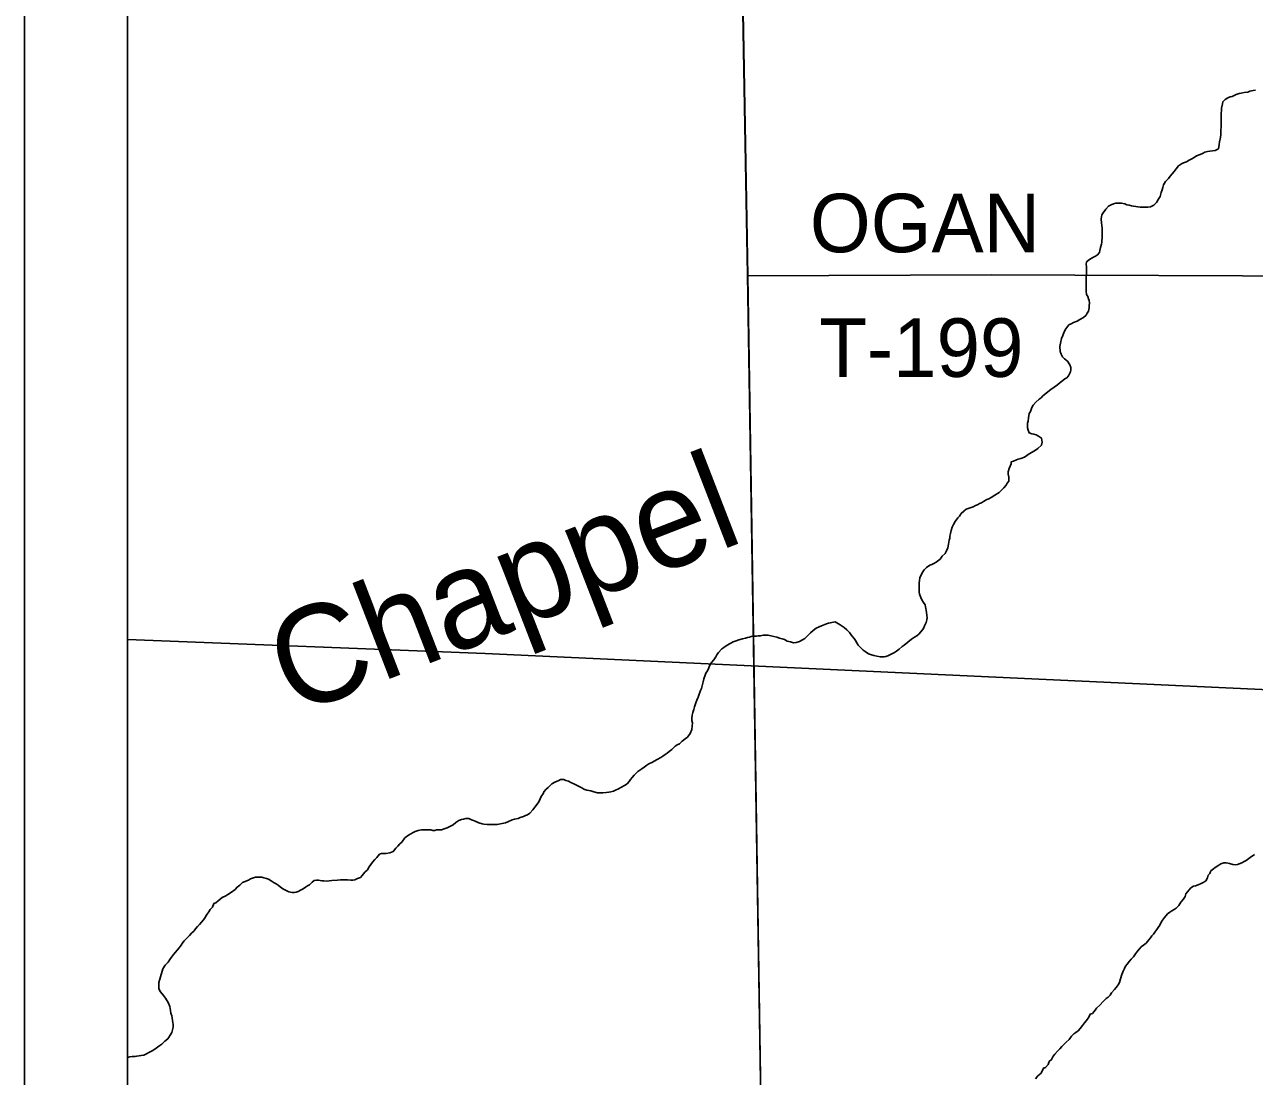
# Model space of a CAD drawing. Extents: x 0 to 34, y 0 to 22.
# Drawn here: x 2 to 3.195, y 17.941 to 18.962 of the extents above; entities that cross this region are included whole.
import ezdxf

# ---------------------------------------------------------------- set-up
doc = ezdxf.new("R2010")
doc.units = 0
for name, color, linetype in [('GM_X_Corporation', 7, 'Continuous'), ('GM_X_Minor_River', 7, 'Continuous'), ('GM_X_Minor_River_Text', 7, 'Continuous'), ('GM_X_Rail_Line', 7, 'Continuous'), ('GM_X_Township_Road', 7, 'Continuous'), ('GM_X_Township_Road_Text', 7, 'Continuous'), ('SH_Data', 7, 'Continuous')]:
    doc.layers.add(name, color=color, linetype=linetype)

msp = doc.modelspace()

# ---------------------------------------------------------------- linework, layer by layer
at = {"layer": 'GM_X_Corporation'}
for points in [[(3.1996, 20.2345), (3.1561, 20.2337), (3.1064, 20.2336), (3.0286, 20.2331), (3.0007, 20.2328), (2.9354, 20.2326), (2.8825, 20.2322), (2.8234, 20.2319), (2.7333, 20.2317), (2.6825, 20.2316), (2.6344, 20.2324), (2.5847, 20.2334), (2.535, 20.2346), (2.5164, 20.2351), (2.4604, 20.2364), (2.3921, 20.2383), (2.333, 20.2398), (2.2833, 20.2411), (2.246, 20.2419), (2.187, 20.2434), (2.1124, 20.2453), (2.1, 20.2456), (2.1, 14.1)], [(3.1996, 20.2345), (3.1561, 20.2337), (3.1064, 20.2336), (3.0286, 20.2331), (3.0007, 20.2328), (2.9354, 20.2326), (2.8825, 20.2322), (2.8234, 20.2319), (2.7333, 20.2317), (2.6825, 20.2316), (2.6883, 19.5017), (2.7024, 18.7188), (2.7184, 17.7156), (2.7304, 16.9599), (2.7477, 15.8824), (2.7366, 15.2014)]]:
    msp.add_lwpolyline(points, dxfattribs=at)
msp.add_lwpolyline([(2.1, 20.2456), (2.1, 15.2121), (2.7366, 15.2014), (2.7477, 15.8824), (2.7304, 16.9599), (2.7184, 17.7156), (2.7024, 18.7188), (2.6883, 19.5017), (2.6825, 20.2316), (2.6344, 20.2324), (2.5847, 20.2334), (2.535, 20.2346), (2.5164, 20.2351), (2.4604, 20.2364), (2.3921, 20.2383), (2.333, 20.2398), (2.2833, 20.2411), (2.246, 20.2419), (2.187, 20.2434), (2.1124, 20.2453)], close=True, dxfattribs=at)
at = {"layer": 'GM_X_Minor_River'}
for points in [[(3.196, 18.8986), (3.1937, 18.8982), (3.1903, 18.8974), (3.1884, 18.8967), (3.185, 18.8963), (3.182, 18.8956), (3.1801, 18.8952), (3.177, 18.8944), (3.1732, 18.8925), (3.1713, 18.8921), (3.169, 18.891), (3.1664, 18.8895), (3.1641, 18.8872), (3.1637, 18.8853), (3.1629, 18.8811), (3.1626, 18.8739), (3.1625, 18.8682), (3.1625, 18.8629), (3.1622, 18.8598), (3.1621, 18.8556), (3.1618, 18.8526), (3.161, 18.8484), (3.1606, 18.8457), (3.1599, 18.8416), (3.1568, 18.84), (3.1542, 18.8397), (3.1515, 18.8393), (3.1492, 18.8389), (3.1466, 18.8382), (3.1443, 18.837), (3.142, 18.8359), (3.1386, 18.8347), (3.1363, 18.8332), (3.134, 18.8317), (3.1313, 18.8306), (3.1287, 18.829), (3.126, 18.8279), (3.1241, 18.8271), (3.1211, 18.8249), (3.1188, 18.8222), (3.1169, 18.8195), (3.115, 18.8173), (3.1131, 18.815), (3.1112, 18.8127), (3.1085, 18.8097), (3.1066, 18.8066), (3.1059, 18.804), (3.1051, 18.8017), (3.1043, 18.799), (3.1032, 18.7952), (3.102, 18.7933), (3.0998, 18.7895), (3.0971, 18.7869), (3.0937, 18.7853), (3.0914, 18.785), (3.0891, 18.785), (3.0868, 18.785), (3.0838, 18.785), (3.0815, 18.7853), (3.0754, 18.7861), (3.0732, 18.7869), (3.0709, 18.7873), (3.069, 18.788), (3.0656, 18.7888), (3.0621, 18.7888), (3.0602, 18.7888), (3.058, 18.788), (3.0557, 18.7873), (3.053, 18.7857), (3.0504, 18.7831), (3.0477, 18.7793), (3.0465, 18.7774), (3.0458, 18.7736), (3.0462, 18.7694), (3.0465, 18.7675), (3.0469, 18.7641), (3.0469, 18.7618), (3.0469, 18.7595), (3.0469, 18.7568), (3.0469, 18.7546), (3.0465, 18.7527), (3.0465, 18.7508), (3.0461, 18.7489), (3.0454, 18.7458), (3.0446, 18.7428), (3.0442, 18.7409), (3.0419, 18.7382), (3.0397, 18.7371), (3.0378, 18.7359), (3.0347, 18.734), (3.0317, 18.7318), (3.0313, 18.7291), (3.0317, 18.7272), (3.0317, 18.7253)], [(3.0317, 18.7253), (3.0317, 18.7222), (3.0317, 18.7203), (3.0313, 18.7184), (3.0313, 18.7162), (3.0313, 18.7139), (3.0313, 18.712), (3.0313, 18.7101), (3.0313, 18.7074), (3.0313, 18.7051), (3.0313, 18.7032), (3.0316, 18.7002), (3.0328, 18.6983), (3.0335, 18.696), (3.0343, 18.6941), (3.0347, 18.6918), (3.0343, 18.6895), (3.0343, 18.6873), (3.0335, 18.6838), (3.0324, 18.6819), (3.0312, 18.68), (3.0286, 18.6778), (3.0252, 18.6759), (3.0225, 18.6743), (3.0191, 18.6728), (3.0168, 18.6717), (3.0145, 18.6705), (3.0115, 18.6667), (3.0099, 18.6637), (3.0088, 18.6603), (3.0073, 18.6572), (3.0065, 18.6527), (3.0058, 18.6496), (3.0061, 18.6447), (3.0069, 18.642), (3.0084, 18.6397), (3.0103, 18.6375), (3.0133, 18.6352), (3.0156, 18.6317), (3.0164, 18.6291), (3.0164, 18.6268), (3.016, 18.6249), (3.0152, 18.623), (3.0141, 18.6211), (3.0126, 18.6192), (3.0107, 18.6181), (3.0088, 18.6165), (3.0061, 18.6146), (3.0034, 18.6124), (3.0004, 18.6101), (2.997, 18.6078), (2.9894, 18.6017), (2.9875, 18.5998), (2.9856, 18.5983), (2.9825, 18.5956), (2.9799, 18.5926), (2.9787, 18.5903), (2.9772, 18.5865), (2.976, 18.5846), (2.9753, 18.5804), (2.9749, 18.577), (2.9745, 18.5751), (2.9745, 18.5725), (2.9745, 18.5705), (2.9749, 18.5683), (2.976, 18.5656), (2.9787, 18.5648), (2.9806, 18.5645), (2.9829, 18.5637), (2.9851, 18.5626), (2.9878, 18.5606), (2.9886, 18.5568), (2.9878, 18.5538), (2.9844, 18.5504), (2.9821, 18.5489), (2.979, 18.547), (2.976, 18.5454), (2.9737, 18.5439), (2.9714, 18.542), (2.968, 18.5409), (2.9654, 18.5401), (2.9635, 18.5394), (2.9608, 18.5382), (2.9585, 18.5375), (2.9585, 18.5356), (2.9566, 18.531), (2.9555, 18.528), (2.9555, 18.5257), (2.9562, 18.5226), (2.9562, 18.5188), (2.9547, 18.5169), (2.9536, 18.515), (2.9513, 18.5124), (2.949, 18.5101), (2.9467, 18.5078), (2.9425, 18.5052), (2.9391, 18.5029), (2.9368, 18.5017), (2.9349, 18.501), (2.9315, 18.4991), (2.9296, 18.4979)], [(2.9296, 18.4979), (2.9277, 18.4972), (2.9258, 18.496), (2.9239, 18.4953), (2.9216, 18.4938), (2.9186, 18.493), (2.9167, 18.4923), (2.9148, 18.4915), (2.9125, 18.4896), (2.9098, 18.4873), (2.9083, 18.485), (2.9068, 18.4831), (2.9041, 18.4797), (2.9026, 18.4767), (2.9011, 18.474), (2.9003, 18.471), (2.8995, 18.4679), (2.8988, 18.4653), (2.8988, 18.4634), (2.8984, 18.4615), (2.8976, 18.4577), (2.8969, 18.4542), (2.8957, 18.4512), (2.8942, 18.4485), (2.8915, 18.4459), (2.8896, 18.4432), (2.8855, 18.4402), (2.8832, 18.439), (2.8813, 18.4379), (2.8794, 18.4371), (2.8763, 18.4349), (2.874, 18.4326), (2.8725, 18.4307), (2.8714, 18.4284), (2.8699, 18.425), (2.8695, 18.4223), (2.8691, 18.42), (2.8691, 18.4166), (2.8691, 18.4132), (2.8691, 18.4113), (2.8695, 18.409), (2.8706, 18.406), (2.8717, 18.4037), (2.8733, 18.401), (2.8748, 18.3987), (2.8751, 18.3968), (2.8763, 18.3915), (2.8767, 18.3885), (2.877, 18.3866), (2.8767, 18.3843), (2.8759, 18.3816), (2.8744, 18.3782), (2.8732, 18.3759), (2.8721, 18.374), (2.869, 18.3706), (2.8668, 18.3687), (2.8645, 18.3672), (2.8618, 18.3653), (2.8546, 18.3596), (2.8527, 18.3584), (2.8496, 18.3558), (2.847, 18.3539), (2.8451, 18.3524), (2.8432, 18.3516), (2.8405, 18.3501), (2.8386, 18.3493), (2.8367, 18.3486), (2.8348, 18.3482), (2.8314, 18.3482), (2.828, 18.3489), (2.8249, 18.3497), (2.8219, 18.3505), (2.82, 18.3512), (2.8166, 18.3535), (2.8147, 18.3547), (2.812, 18.3573), (2.8097, 18.3596), (2.8086, 18.3619), (2.8071, 18.3642), (2.806, 18.3661), (2.8037, 18.3687), (2.8014, 18.3718), (2.7987, 18.3745), (2.7961, 18.3767), (2.7942, 18.3779), (2.7923, 18.3794), (2.7874, 18.3821), (2.7843, 18.3817), (2.7809, 18.3809), (2.779, 18.3802), (2.7759, 18.379), (2.7741, 18.3783), (2.7718, 18.3775), (2.7691, 18.376), (2.7661, 18.3737), (2.7634, 18.3714), (2.7607, 18.3688), (2.7581, 18.3661), (2.7558, 18.3646), (2.7528, 18.3631), (2.7497, 18.3623)], [(2.7497, 18.3623), (2.7471, 18.3619), (2.744, 18.3627), (2.741, 18.3635), (2.7383, 18.365), (2.736, 18.3658), (2.7334, 18.3665), (2.7307, 18.3673), (2.725, 18.3688), (2.7224, 18.3692), (2.7193, 18.3692), (2.7174, 18.3692), (2.7151, 18.3688), (2.7129, 18.3688), (2.711, 18.3684), (2.7087, 18.3684), (2.706, 18.3681), (2.7041, 18.3673), (2.7022, 18.3669), (2.7003, 18.3665), (2.6973, 18.3658), (2.6939, 18.3646), (2.6912, 18.3639), (2.6885, 18.3628), (2.6855, 18.3612), (2.6825, 18.3597), (2.6794, 18.3574), (2.6775, 18.3559), (2.6741, 18.3525), (2.6726, 18.3502), (2.6714, 18.3483), (2.6695, 18.3453), (2.6672, 18.3426), (2.6653, 18.3396), (2.6646, 18.3377), (2.6634, 18.3346), (2.6619, 18.3323), (2.6611, 18.3304), (2.66, 18.327), (2.6592, 18.324), (2.6577, 18.3175), (2.6566, 18.3156), (2.655, 18.3111), (2.6543, 18.3092), (2.6531, 18.3061), (2.652, 18.3035), (2.6516, 18.3015), (2.6509, 18.2996), (2.6501, 18.297), (2.6493, 18.2943), (2.6486, 18.2917), (2.6482, 18.2886), (2.6482, 18.2863), (2.6489, 18.2841), (2.6482, 18.2776), (2.6466, 18.2738), (2.644, 18.2704), (2.6417, 18.2685), (2.6387, 18.2662), (2.6364, 18.2639), (2.6341, 18.2628), (2.6322, 18.2616), (2.6288, 18.2582), (2.6261, 18.2563), (2.6242, 18.2548), (2.6223, 18.2533), (2.62, 18.2518), (2.6181, 18.2506), (2.6147, 18.2487), (2.6094, 18.2457), (2.6063, 18.2442), (2.6044, 18.243), (2.6018, 18.2411), (2.5995, 18.2396), (2.5957, 18.2369), (2.5923, 18.2335), (2.5904, 18.2312), (2.5888, 18.229), (2.5873, 18.2271), (2.5854, 18.2248), (2.5828, 18.2233), (2.5793, 18.2214), (2.5771, 18.2202), (2.574, 18.2187), (2.5721, 18.2179), (2.5694, 18.2172), (2.5675, 18.2168), (2.5649, 18.2164), (2.5618, 18.2161), (2.5592, 18.2161), (2.5565, 18.2161), (2.5531, 18.2172), (2.5501, 18.218), (2.5482, 18.2183), (2.5463, 18.2187), (2.5432, 18.2199), (2.5413, 18.221), (2.5368, 18.2233), (2.5337, 18.2248), (2.5307, 18.2263), (2.5284, 18.2275)], [(2.5284, 18.2275), (2.5258, 18.2283), (2.5239, 18.229), (2.5208, 18.229), (2.5189, 18.2283), (2.5151, 18.2267), (2.5121, 18.2248), (2.5087, 18.2214), (2.5068, 18.2199), (2.5045, 18.2172), (2.5037, 18.2153), (2.5022, 18.2134), (2.501, 18.2104), (2.4995, 18.2074), (2.498, 18.2051), (2.4957, 18.2024), (2.4938, 18.1998), (2.4908, 18.1963), (2.4885, 18.1948), (2.4866, 18.1941), (2.4847, 18.1933), (2.4813, 18.1922), (2.4794, 18.1914), (2.4759, 18.1906), (2.4737, 18.1899), (2.4695, 18.188), (2.4672, 18.1872), (2.4607, 18.1857), (2.4588, 18.1853), (2.4569, 18.1853), (2.4531, 18.1853), (2.4512, 18.1853), (2.4493, 18.1853), (2.4463, 18.1857), (2.4444, 18.1861), (2.4414, 18.1872), (2.4379, 18.1888), (2.436, 18.1892), (2.4341, 18.1899), (2.4315, 18.1911), (2.4288, 18.1911), (2.4265, 18.1907), (2.4246, 18.1903), (2.422, 18.1892), (2.4189, 18.1873), (2.4163, 18.185), (2.4144, 18.1842), (2.4106, 18.1823), (2.4075, 18.1812), (2.4049, 18.1804), (2.4022, 18.1801), (2.4003, 18.1801), (2.3984, 18.1797), (2.3965, 18.1797), (2.3946, 18.1801), (2.3923, 18.1801), (2.3904, 18.1801), (2.3885, 18.1804), (2.3855, 18.1801), (2.3825, 18.1797), (2.3794, 18.1785), (2.3775, 18.1778), (2.373, 18.1751), (2.3695, 18.1725), (2.3665, 18.1683), (2.3646, 18.1668), (2.3627, 18.1645), (2.3608, 18.1626), (2.3581, 18.1592), (2.3547, 18.158), (2.3513, 18.1573), (2.3494, 18.1573), (2.3467, 18.1573), (2.3448, 18.1565), (2.3422, 18.1535), (2.3402, 18.1516), (2.338, 18.1489), (2.3364, 18.1466), (2.3349, 18.1444), (2.333, 18.1413), (2.3307, 18.139), (2.3281, 18.136), (2.3262, 18.1341), (2.3235, 18.133), (2.3208, 18.1318), (2.3189, 18.1314), (2.317, 18.1314), (2.3136, 18.1318), (2.3117, 18.1318), (2.3087, 18.1318), (2.3068, 18.1318), (2.3041, 18.1315), (2.2984, 18.1311), (2.2958, 18.1307), (2.2939, 18.1303), (2.2908, 18.1307), (2.2889, 18.1307), (2.2855, 18.1315), (2.2836, 18.1315), (2.2813, 18.1311), (2.2794, 18.1296)], [(3.1948, 18.1562), (3.1907, 18.1535), (3.1869, 18.1505), (3.185, 18.1494), (3.1827, 18.1482), (3.1785, 18.1467), (3.1762, 18.1463), (3.1739, 18.1467), (3.1705, 18.1475), (3.1675, 18.1482), (3.1652, 18.1482), (3.1622, 18.1471), (3.1603, 18.146), (3.1568, 18.1437), (3.1549, 18.1425), (3.1526, 18.1403), (3.1515, 18.138), (3.15, 18.1361), (3.1492, 18.1338), (3.1477, 18.1307), (3.1458, 18.1296), (3.1431, 18.1281), (3.1401, 18.127), (3.1374, 18.1258), (3.1355, 18.1254), (3.1329, 18.1239), (3.1283, 18.1182), (3.1275, 18.1156), (3.1256, 18.1125), (3.1234, 18.1099), (3.1214, 18.1068), (3.1188, 18.1041), (3.1169, 18.103), (3.1146, 18.1015), (3.1127, 18.1004), (3.1104, 18.0988), (3.1074, 18.095), (3.1055, 18.0924), (3.104, 18.0901), (3.1028, 18.0878), (3.1013, 18.0855), (3.1001, 18.0836), (3.0982, 18.081), (3.0967, 18.0791), (3.0952, 18.0772), (3.0937, 18.0753), (3.0922, 18.0734), (3.0895, 18.0703), (3.0872, 18.0684), (3.0849, 18.0665), (3.083, 18.0646), (3.0811, 18.0623), (3.0792, 18.0597), (3.0773, 18.057), (3.075, 18.0547), (3.0735, 18.0528), (3.0712, 18.0498), (3.0697, 18.0479), (3.0686, 18.0456), (3.0674, 18.043), (3.0659, 18.0399), (3.0648, 18.0357), (3.0636, 18.0319), (3.0625, 18.0297), (3.0606, 18.027), (3.059, 18.0251), (3.056, 18.0221), (3.0545, 18.0198), (3.0526, 18.0179), (3.0507, 18.0164), (3.0476, 18.0133), (3.045, 18.0103), (3.0415, 18.0072), (3.04, 18.005)], [(2.2794, 18.1296), (2.2768, 18.1269), (2.2749, 18.1258), (2.273, 18.1246), (2.2707, 18.1231), (2.2688, 18.122), (2.2657, 18.1205), (2.2638, 18.1197), (2.2619, 18.1193), (2.26, 18.1193), (2.2566, 18.1201), (2.254, 18.1212), (2.2509, 18.1231), (2.2483, 18.125), (2.2464, 18.1266), (2.2445, 18.1277), (2.2426, 18.1288), (2.2395, 18.1307), (2.2369, 18.1323), (2.235, 18.133), (2.2323, 18.1338), (2.2304, 18.1342), (2.2281, 18.1342), (2.2262, 18.1342), (2.2243, 18.1342), (2.2213, 18.1334), (2.2194, 18.1327), (2.2175, 18.1315), (2.2118, 18.1292), (2.2091, 18.1266), (2.2065, 18.1247), (2.2046, 18.1224), (2.2011, 18.1197), (2.1973, 18.1175), (2.1954, 18.1163), (2.192, 18.1144), (2.1882, 18.1114), (2.1859, 18.1095), (2.184, 18.1087), (2.1825, 18.1053), (2.1802, 18.103), (2.1791, 18.1007), (2.1772, 18.0981), (2.1749, 18.0943), (2.1722, 18.0909), (2.17, 18.0882), (2.1681, 18.0863), (2.1661, 18.084), (2.1646, 18.0821), (2.1623, 18.0798), (2.1601, 18.0776), (2.157, 18.0745), (2.1551, 18.0726), (2.1536, 18.0707), (2.1521, 18.0684), (2.1502, 18.0658), (2.1483, 18.0635), (2.1467, 18.0616), (2.1448, 18.0593), (2.1426, 18.0567), (2.141, 18.0544), (2.1395, 18.0517), (2.1365, 18.0487), (2.1342, 18.0453), (2.1315, 18.0354), (2.1304, 18.0319), (2.1304, 18.0285), (2.1304, 18.0259), (2.1319, 18.0228), (2.1349, 18.0194), (2.1368, 18.0167), (2.1395, 18.0125), (2.141, 18.0087), (2.1414, 18.0068), (2.1417, 18.0049), (2.1421, 18.0023), (2.1429, 17.9996), (2.1433, 17.9977), (2.1436, 17.995), (2.144, 17.9931), (2.1444, 17.9912), (2.1444, 17.9886), (2.1432, 17.9836), (2.1421, 17.9817), (2.1391, 17.9772), (2.1364, 17.9749), (2.1334, 17.9722), (2.1315, 17.9707), (2.1292, 17.9692), (2.1265, 17.9673), (2.1238, 17.9658), (2.1208, 17.9639), (2.1185, 17.9627), (2.1159, 17.9616), (2.1132, 17.9612), (2.1113, 17.9608), (2.109, 17.9605), (2.1071, 17.9601), (2.1045, 17.9601), (2.1022, 17.9597), (2.1, 17.9593)], [(3.04, 18.005), (3.0374, 18.0019), (3.0351, 18.0012), (3.0339, 17.9985), (3.0317, 17.9951), (3.0298, 17.9928), (3.0278, 17.9901), (3.0256, 17.9875), (3.0237, 17.9852), (3.0214, 17.9833), (3.0195, 17.9821), (3.0172, 17.9799), (3.0149, 17.9768), (3.0119, 17.9742), (3.0077, 17.97), (3.0058, 17.9677), (3.0035, 17.9654), (3.0008, 17.9624), (2.9993, 17.9605), (2.9978, 17.9571), (2.9955, 17.9552), (2.9944, 17.9525), (2.9917, 17.9495), (2.9898, 17.9487), (2.9875, 17.9441), (2.9845, 17.9415), (2.9822, 17.9384)]]:
    msp.add_lwpolyline(points, dxfattribs=at)
at = {"layer": 'GM_X_Rail_Line'}
msp.add_lwpolyline([(2.1, 18.3652), (2.4476, 18.3515), (3.7542, 18.2908), (4.7355, 18.2536), (4.912, 18.2502), (5.0326, 18.2535), (5.2097, 18.2563), (5.4881, 18.3005), (6.2957, 18.4383), (6.9068, 18.5576), (7.5368, 18.6745), (7.9374, 18.7476)], dxfattribs=at)
at = {"layer": 'GM_X_Township_Road'}
for points in [[(2.7186, 17.715), (2.7026, 18.7182), (2.697, 19.0294)], [(2.7026, 18.7182), (2.939, 18.7191), (3.2644, 18.7179), (3.5814, 18.719), (3.738, 18.7184), (3.796, 18.7166), (3.8897, 18.7163), (3.9185, 18.7162), (3.9265, 18.7154), (3.9481, 18.7058), (4.4619, 18.4832), (4.4984, 18.4668), (4.5115, 18.459), (4.5164, 18.4527)]]:
    msp.add_lwpolyline(points, dxfattribs=at)
at = {"layer": 'SH_Data'}
for p, q in [((2, 21), (2, 14)), ((2.1, 20.9), (2.1, 14.1))]:
    msp.add_line(p, q, dxfattribs=at)

# ---------------------------------------------------------------- texts
at = {"layer": 'GM_X_Minor_River_Text'}
msp.add_text('Chappel', height=0.09475, rotation=21.1807, dxfattribs=at).set_placement((2.2611, 18.2906))
at = {"layer": 'GM_X_Township_Road_Text'}
for s, p in [('OGAN', (2.7629, 18.7411)), ('T-199', (2.772, 18.6201))]:
    msp.add_text(s, height=0.05682, rotation=0, dxfattribs=at).set_placement(p)

doc.saveas('drawing.dxf')
